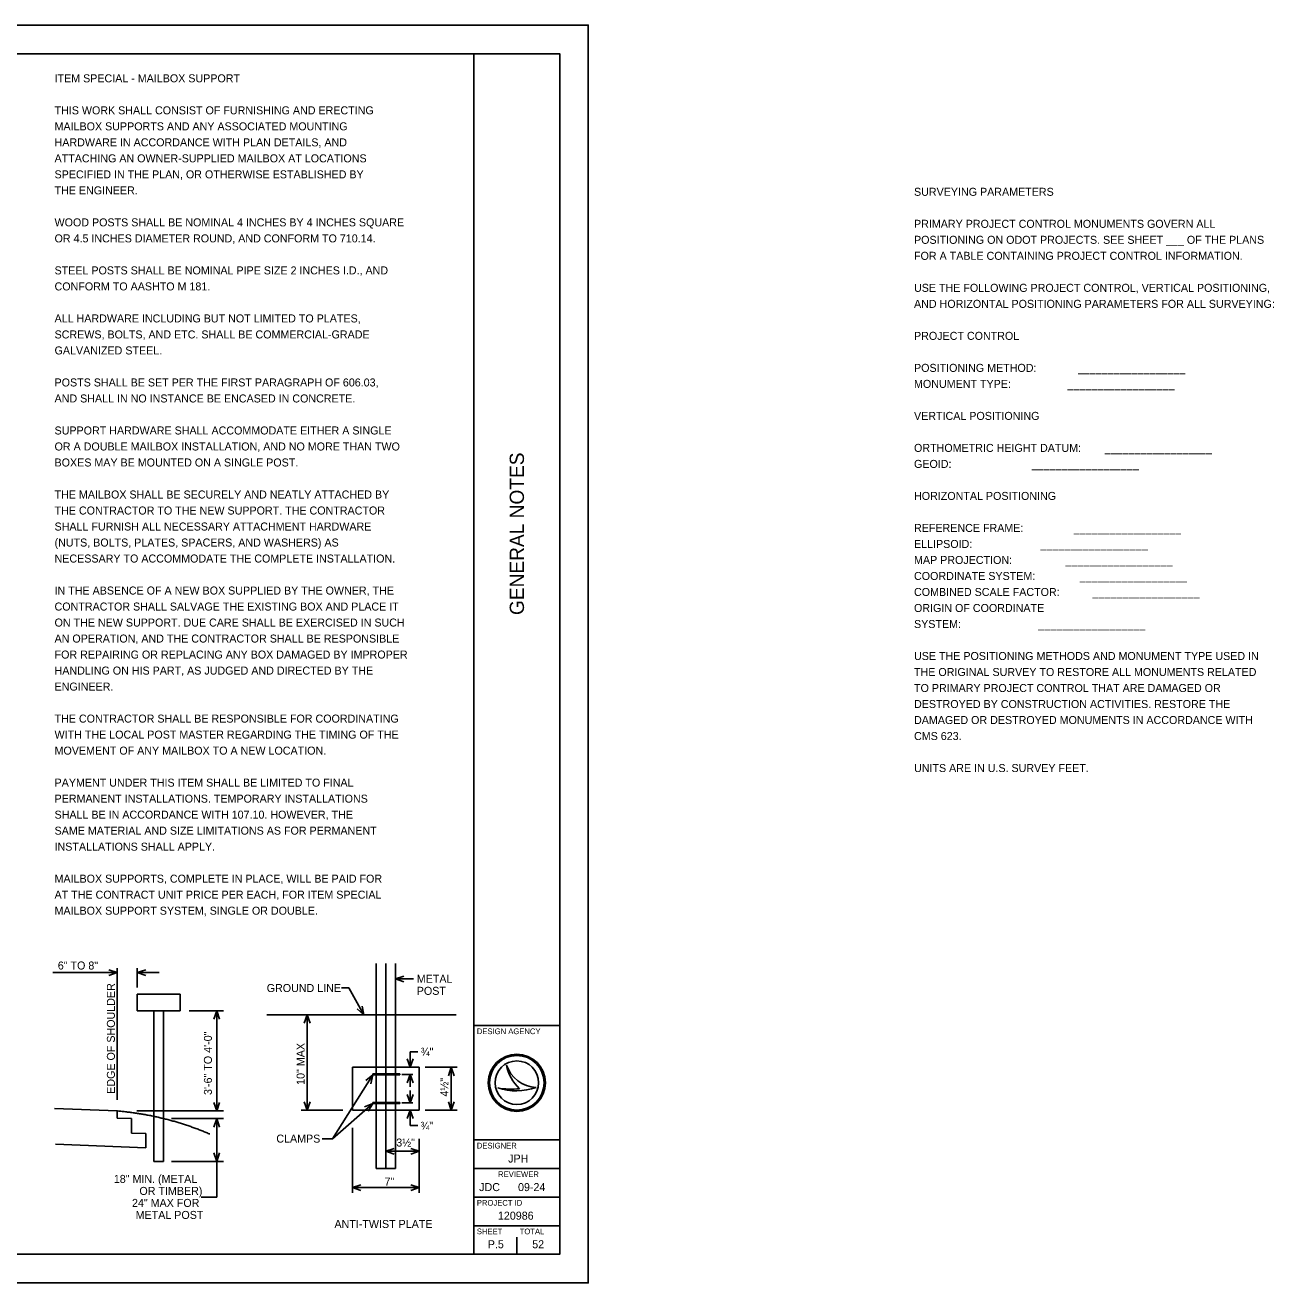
# Model space of a CAD drawing. Extents: x -46.8 to 46, y -4.4 to 22.
# Drawn here: x 24.15 to 46, y 0 to 22 of the extents above; entities that cross this region are included whole.
import ezdxf

# ---------------------------------------------------------------- set-up
doc = ezdxf.new("R2010")
doc.units = 0
for name, color, linetype in [('RD_P_Cells', 7, 'Continuous'), ('SH_Border', 7, 'Continuous'), ('SH_Cut_Line', 7, 'Continuous'), ('SH_Data', 7, 'Continuous'), ('SH_Text', 7, 'Continuous'), ('TX_P_1', 7, 'Continuous'), ('TX_P_Misc', 7, 'Continuous'), ('XS_P_Finished_Grade', 7, 'Continuous'), ('XS_P_Pavt_Surface', 7, 'Continuous')]:
    doc.layers.add(name, color=color, linetype=linetype)

msp = doc.modelspace()

# ---------------------------------------------------------------- linework, layer by layer
at = {"layer": 'RD_P_Cells'}
for p, q in [((30.291, 1.999), (30.291, 5.585)), ((30.457, 1.999), (30.457, 5.585)), ((30.624, 1.999), (30.624, 5.585)), ((30.941, 5.315), (30.624, 5.315)), ((29.684, 5.158), (29.809, 5.158)), ((29.809, 5.158), (30.07, 4.688)), ((26.106, 4.758), (26.106, 5.05)), ((26.106, 5.05), (26.856, 5.05)), ((26.856, 4.758), (26.856, 5.05)), ((26.106, 4.758), (26.856, 4.758)), ((26.398, 4.758), (26.398, 2.125)), ((26.565, 4.758), (26.565, 2.125)), ((31.689, 4.688), (28.373, 4.688)), ((29.081, 4.688), (29.081, 3.021)), ((30.883, 3.771), (30.883, 4.039)), ((30.883, 4.039), (31.019, 4.039)), ((31.041, 3.771), (29.874, 3.771)), ((29.874, 3.771), (29.874, 3.021)), ((31.041, 3.771), (31.041, 3.021)), ((31.143, 3.771), (31.703, 3.771)), ((31.603, 3.771), (31.603, 3.021)), ((30.23, 3.636), (29.523, 2.518)), ((30.701, 3.656), (30.23, 3.656)), ((30.23, 3.656), (30.23, 3.636)), ((30.701, 3.636), (30.23, 3.636)), ((30.701, 3.656), (30.701, 3.636)), ((30.738, 3.646), (30.927, 3.646)), ((30.883, 3.43), (30.883, 3.646)), ((30.883, 3.146), (30.883, 3.362)), ((30.23, 3.136), (29.523, 2.518)), ((30.701, 3.156), (30.23, 3.156)), ((30.23, 3.156), (30.23, 3.136)), ((30.701, 3.136), (30.23, 3.136)), ((30.701, 3.156), (30.701, 3.136)), ((30.738, 3.146), (30.927, 3.146)), ((29.704, 3.021), (28.974, 3.021)), ((31.041, 3.021), (29.874, 3.021)), ((30.883, 2.753), (30.883, 3.021)), ((31.143, 3.021), (31.703, 3.021)), ((29.874, 2.714), (29.874, 1.575)), ((30.883, 2.753), (31.019, 2.753)), ((29.523, 2.518), (29.346, 2.518)), ((31.041, 2.522), (31.041, 1.575)), ((30.457, 2.301), (31.041, 2.301)), ((26.398, 2.125), (26.565, 2.125)), ((30.291, 1.999), (30.624, 1.999)), ((29.874, 1.667), (31.041, 1.667))]:
    msp.add_line(p, q, dxfattribs=at)
at = {"layer": 'SH_Border'}
for p, q in [((32, 0.5), (32, 21.5)), ((32, 4.5), (33.5, 4.5)), ((32, 2.5), (33.5, 2.5)), ((32, 2), (33.5, 2)), ((32, 1.5), (33.5, 1.5)), ((32, 1), (33.5, 1))]:
    msp.add_line(p, q, dxfattribs=at)
msp.add_lwpolyline([(1.5, 21.5), (33.5, 21.5), (33.5, 0.5), (1.5, 0.5)], close=True, dxfattribs=at)
at = {"layer": 'SH_Cut_Line'}
msp.add_lwpolyline([(0, 0), (34, 0), (34, 22), (0, 22)], close=True, dxfattribs=at)
at = {"layer": 'SH_Data'}
for p, q in [((32.567, 3.81), (32.567, 3.81)), ((32.417, 3.41), (32.417, 3.41)), ((32.75, 3.5), (32.75, 3.5)), ((33.087, 3.419), (33.087, 3.419)), ((32.375, 0.675), (32.375, 0.675)), ((32.75, 0.5), (32.75, 0.8))]:
    msp.add_line(p, q, dxfattribs=at)
for radius in [0.5, 0.477, 0.477, 0.382]:
    msp.add_circle((32.75, 3.5), radius, dxfattribs=at)
for centre, radius, start, end in [((33.116, 3.998), 0.58, 198.9257, 198.9319), ((33.347, 3.97), 0.796, 191.6379, 191.6421), ((33.116, 3.998), 0.58, 198.9319, 267.1657), ((33.347, 3.97), 0.796, 191.6421, 226.0947), ((32.739, 4.37), 1.013, 251.4576, 290.0832), ((32.648, 4.654), 1.266, 259.4964, 259.4995), ((32.739, 4.37), 1.013, 251.4527, 251.4576), ((32.648, 4.654), 1.266, 259.4995, 276.6672)]:
    msp.add_arc(centre, radius, start, end, dxfattribs=at)
at = {"layer": 'TX_P_1'}
for p, q in [((25.758, 3.203), (25.758, 5.503)), ((26.106, 5.165), (26.106, 5.503)), ((25.758, 5.427), (24.631, 5.427)), ((25.758, 5.427), (25.61, 5.477)), ((25.758, 5.427), (25.61, 5.377)), ((26.106, 5.427), (26.255, 5.477)), ((26.106, 5.427), (26.492, 5.427)), ((26.106, 5.427), (26.255, 5.377)), ((30.624, 5.315), (30.772, 5.365)), ((30.624, 5.315), (30.772, 5.265)), ((30.07, 4.688), (30.042, 4.842)), ((27.013, 4.758), (27.617, 4.758)), ((27.499, 4.758), (27.449, 4.61)), ((27.499, 4.758), (27.499, 3.007)), ((27.499, 4.758), (27.549, 4.61)), ((29.081, 4.688), (29.031, 4.54)), ((29.081, 4.688), (29.131, 4.54)), ((30.07, 4.688), (29.954, 4.793)), ((30.883, 3.771), (30.833, 3.919)), ((30.883, 3.771), (30.933, 3.919)), ((31.603, 3.771), (31.553, 3.623)), ((31.603, 3.771), (31.653, 3.623)), ((30.23, 3.636), (30.108, 3.538)), ((30.23, 3.636), (30.193, 3.484)), ((30.883, 3.646), (30.833, 3.498)), ((30.883, 3.646), (30.933, 3.498)), ((27.499, 3.007), (27.449, 3.155)), ((27.499, 3.007), (27.549, 3.155)), ((29.081, 3.021), (29.031, 3.169)), ((29.081, 3.021), (29.131, 3.169)), ((30.23, 3.136), (30.085, 3.076)), ((30.23, 3.136), (30.151, 3.001)), ((30.883, 3.146), (30.833, 3.294)), ((30.883, 3.146), (30.933, 3.294)), ((31.603, 3.021), (31.553, 3.169)), ((31.603, 3.021), (31.653, 3.169)), ((26.1, 3.007), (27.617, 3.007)), ((26.706, 2.875), (27.617, 2.875)), ((27.499, 2.875), (27.449, 2.726)), ((27.499, 2.875), (27.499, 1.499)), ((27.499, 2.875), (27.549, 2.726)), ((30.883, 3.021), (30.833, 2.873)), ((30.883, 3.021), (30.933, 2.873)), ((27.499, 2.125), (27.449, 2.273)), ((27.499, 2.125), (27.549, 2.273)), ((30.457, 2.301), (30.606, 2.351)), ((30.457, 2.301), (30.606, 2.251)), ((31.041, 2.301), (30.893, 2.351)), ((31.041, 2.301), (30.893, 2.251)), ((26.706, 2.125), (27.617, 2.125)), ((29.874, 1.667), (30.022, 1.717)), ((29.874, 1.667), (30.022, 1.617)), ((31.041, 1.667), (30.893, 1.717)), ((31.041, 1.667), (30.893, 1.617)), ((27.499, 1.499), (27.226, 1.499))]:
    msp.add_line(p, q, dxfattribs=at)
at = {"layer": 'XS_P_Finished_Grade'}
msp.add_spline([(25.743, 3.008), (25.782, 3.005), (25.821, 3.001), (25.86, 2.997), (25.899, 2.993), (25.938, 2.988), (25.976, 2.984), (26.015, 2.978), (26.053, 2.973), (26.092, 2.968), (26.13, 2.962), (26.168, 2.956), (26.206, 2.949), (26.244, 2.942), (26.282, 2.936), (26.32, 2.928), (26.358, 2.921), (26.396, 2.913), (26.434, 2.905), (26.471, 2.897), (26.509, 2.888), (26.546, 2.879), (26.583, 2.87), (26.621, 2.861), (26.658, 2.851), (26.695, 2.841), (26.732, 2.831), (26.769, 2.82), (26.806, 2.809), (26.843, 2.798), (26.88, 2.787), (26.916, 2.775), (26.953, 2.763), (26.99, 2.751), (27.026, 2.739), (27.062, 2.726), (27.099, 2.713), (27.135, 2.7), (27.171, 2.686), (27.207, 2.672), (27.243, 2.658), (27.279, 2.644), (27.315, 2.629), (27.351, 2.614), (27.377, 2.604)], degree=3, dxfattribs=at)
at = {"layer": 'XS_P_Pavt_Surface'}
for p, q in [((24.659, 3.051), (25.758, 3.007)), ((25.758, 3.007), (25.758, 2.882)), ((25.758, 2.882), (26.008, 2.872)), ((26.008, 2.872), (26.008, 2.621)), ((24.676, 2.425), (26.258, 2.361)), ((26.008, 2.621), (26.258, 2.611)), ((26.258, 2.611), (26.258, 2.361))]:
    msp.add_line(p, q, dxfattribs=at)

# ---------------------------------------------------------------- texts
at = {"layer": 'RD_P_Cells'}
for s, p in [('METAL', (30.999, 5.248)), ('GROUND LINE', (28.373, 5.087)), ('POST', (30.999, 5.038)), ('¾"', (31.067, 3.972)), ('¾"', (31.063, 2.677)), ('CLAMPS', (28.541, 2.453)), ('3½"', (30.64, 2.384)), ('7"', (30.434, 1.701))]:
    msp.add_text(s, height=0.14, dxfattribs=at).set_placement(p)
for s, p in [('10" MAX', (29.036, 3.463)), ('4½"', (31.551, 3.259))]:
    msp.add_text(s, height=0.14, rotation=90, dxfattribs=at).set_placement(p)
at = {"layer": 'SH_Data'}
msp.add_text('GENERAL NOTES', height=0.25, rotation=90, dxfattribs=at).set_placement((32.875, 11.682))
for s, height, p in [('DESIGN AGENCY', 0.1, (32.05, 4.35)), ('DESIGNER', 0.1, (32.05, 2.35)), ('JPH', 0.14, (32.598, 2.105)), ('REVIEWER', 0.1, (32.422, 1.85)), ('JDC', 0.14, (32.091, 1.605)), ('09-24', 0.14, (32.771, 1.605)), ('PROJECT ID', 0.1, (32.05, 1.35)), ('120986', 0.14, (32.419, 1.105)), ('SHEET', 0.1, (32.05, 0.85)), ('TOTAL', 0.1, (32.8, 0.85)), ('P.5', 0.14, (32.241, 0.605)), ('52', 0.14, (33.019, 0.605))]:
    msp.add_text(s, height=height, dxfattribs=at).set_placement(p)
at = {"layer": 'SH_Text'}
for s, p in [('ITEM SPECIAL - MAILBOX SUPPORT', (24.66, 21)), ('THIS WORK SHALL CONSIST OF FURNISHING AND ERECTING', (24.66, 20.44)), ('MAILBOX SUPPORTS AND ANY ASSOCIATED MOUNTING', (24.66, 20.16)), ('HARDWARE IN ACCORDANCE WITH PLAN DETAILS, AND', (24.66, 19.88)), ('ATTACHING AN OWNER-SUPPLIED MAILBOX AT LOCATIONS', (24.66, 19.6)), ('SPECIFIED IN THE PLAN, OR OTHERWISE ESTABLISHED BY', (24.66, 19.32)), ('THE ENGINEER.', (24.66, 19.04)), ('SURVEYING PARAMETERS', (39.701, 19.015)), ('WOOD POSTS SHALL BE NOMINAL 4 INCHES BY 4 INCHES SQUARE', (24.66, 18.48)), ('PRIMARY PROJECT CONTROL MONUMENTS GOVERN ALL', (39.701, 18.455)), ('OR 4.5 INCHES DIAMETER ROUND, AND CONFORM TO 710.14.', (24.66, 18.2)), ('POSITIONING ON ODOT PROJECTS. SEE SHEET ___ OF THE PLANS', (39.701, 18.175)), ('FOR A TABLE CONTAINING PROJECT CONTROL INFORMATION.', (39.701, 17.895)), ('STEEL POSTS SHALL BE NOMINAL PIPE SIZE 2 INCHES I.D., AND', (24.66, 17.64)), ('CONFORM TO AASHTO M 181.', (24.66, 17.36)), ('USE THE FOLLOWING PROJECT CONTROL, VERTICAL POSITIONING,', (39.701, 17.335)), ('AND HORIZONTAL POSITIONING PARAMETERS FOR ALL SURVEYING:', (39.701, 17.055)), ('ALL HARDWARE INCLUDING BUT NOT LIMITED TO PLATES,', (24.66, 16.8)), ('SCREWS, BOLTS, AND ETC. SHALL BE COMMERCIAL-GRADE', (24.66, 16.52)), ('PROJECT CONTROL', (39.701, 16.495)), ('GALVANIZED STEEL.', (24.66, 16.24)), ('POSITIONING METHOD:              __________________', (39.701, 15.935)), ('POSTS SHALL BE SET PER THE FIRST PARAGRAPH OF 606.03,', (24.66, 15.68)), ('MONUMENT TYPE:                   __________________', (39.701, 15.655)), ('AND SHALL IN NO INSTANCE BE ENCASED IN CONCRETE.', (24.66, 15.4)), ('VERTICAL POSITIONING', (39.701, 15.095)), ('SUPPORT HARDWARE SHALL ACCOMMODATE EITHER A SINGLE', (24.66, 14.84)), ('OR A DOUBLE MAILBOX INSTALLATION, AND NO MORE THAN TWO', (24.66, 14.56)), ('ORTHOMETRIC HEIGHT DATUM:        __________________', (39.701, 14.535)), ('BOXES MAY BE MOUNTED ON A SINGLE POST.', (24.66, 14.28)), ('GEOID:                           __________________', (39.701, 14.255)), ('THE MAILBOX SHALL BE SECURELY AND NEATLY ATTACHED BY', (24.66, 13.72)), ('HORIZONTAL POSITIONING', (39.701, 13.695)), ('THE CONTRACTOR TO THE NEW SUPPORT. THE CONTRACTOR', (24.66, 13.44)), ('SHALL FURNISH ALL NECESSARY ATTACHMENT HARDWARE', (24.66, 13.16)), ('REFERENCE FRAME:                 __________________', (39.701, 13.135)), ('(NUTS, BOLTS, PLATES, SPACERS, AND WASHERS) AS', (24.66, 12.88)), ('ELLIPSOID:                       __________________', (39.701, 12.855)), ('NECESSARY TO ACCOMMODATE THE COMPLETE INSTALLATION.', (24.66, 12.6)), ('MAP PROJECTION:                  __________________', (39.701, 12.575)), ('COORDINATE SYSTEM:               __________________', (39.701, 12.295)), ('IN THE ABSENCE OF A NEW BOX SUPPLIED BY THE OWNER, THE', (24.66, 12.04)), ('COMBINED SCALE FACTOR:           __________________', (39.701, 12.015)), ('CONTRACTOR SHALL SALVAGE THE EXISTING BOX AND PLACE IT', (24.66, 11.76)), ('ORIGIN OF COORDINATE', (39.701, 11.735)), ('ON THE NEW SUPPORT. DUE CARE SHALL BE EXERCISED IN SUCH', (24.66, 11.48)), ('SYSTEM:                          __________________', (39.701, 11.455)), ('AN OPERATION, AND THE CONTRACTOR SHALL BE RESPONSIBLE', (24.66, 11.2)), ('FOR REPAIRING OR REPLACING ANY BOX DAMAGED BY IMPROPER', (24.66, 10.92)), ('USE THE POSITIONING METHODS AND MONUMENT TYPE USED IN', (39.701, 10.895)), ('HANDLING ON HIS PART, AS JUDGED AND DIRECTED BY THE', (24.66, 10.64)), ('THE ORIGINAL SURVEY TO RESTORE ALL MONUMENTS RELATED', (39.701, 10.615)), ('ENGINEER.', (24.66, 10.36)), ('TO PRIMARY PROJECT CONTROL THAT ARE DAMAGED OR', (39.701, 10.335)), ('DESTROYED BY CONSTRUCTION ACTIVITIES. RESTORE THE', (39.701, 10.055)), ('THE CONTRACTOR SHALL BE RESPONSIBLE FOR COORDINATING', (24.66, 9.8)), ('DAMAGED OR DESTROYED MONUMENTS IN ACCORDANCE WITH', (39.701, 9.775)), ('WITH THE LOCAL POST MASTER REGARDING THE TIMING OF THE', (24.66, 9.52)), ('CMS 623.', (39.701, 9.495)), ('MOVEMENT OF ANY MAILBOX TO A NEW LOCATION.', (24.66, 9.24)), ('UNITS ARE IN U.S. SURVEY FEET.', (39.701, 8.935)), ('PAYMENT UNDER THIS ITEM SHALL BE LIMITED TO FINAL', (24.66, 8.68)), ('PERMANENT INSTALLATIONS. TEMPORARY INSTALLATIONS', (24.66, 8.4)), ('SHALL BE IN ACCORDANCE WITH 107.10. HOWEVER, THE', (24.66, 8.12)), ('SAME MATERIAL AND SIZE LIMITATIONS AS FOR PERMANENT', (24.66, 7.84)), ('INSTALLATIONS SHALL APPLY.', (24.66, 7.56)), ('MAILBOX SUPPORTS, COMPLETE IN PLACE, WILL BE PAID FOR', (24.66, 7)), ('AT THE CONTRACT UNIT PRICE PER EACH, FOR ITEM SPECIAL', (24.66, 6.72)), ('MAILBOX SUPPORT SYSTEM, SINGLE OR DOUBLE.', (24.66, 6.44))]:
    msp.add_text(s, height=0.14, dxfattribs=at).set_placement(p)
at = {"layer": 'TX_P_Misc'}
for s, p in [('6" TO 8"', (24.717, 5.481)), ('18" MIN. (METAL', (25.697, 1.748)), ('OR TIMBER)', (26.145, 1.538)), ('24" MAX FOR', (26.015, 1.328)), ('METAL POST', (26.079, 1.118)), ('ANTI-TWIST PLATE', (29.558, 0.96))]:
    msp.add_text(s, height=0.14, dxfattribs=at).set_placement(p)
for s, p in [('EDGE OF SHOULDER', (25.716, 3.307)), ('3\'-6" TO 4\'-0"', (27.414, 3.286))]:
    msp.add_text(s, height=0.14, rotation=90, dxfattribs=at).set_placement(p)

doc.saveas('drawing.dxf')
